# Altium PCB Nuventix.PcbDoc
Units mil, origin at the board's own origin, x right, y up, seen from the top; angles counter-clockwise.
Board outline 1849.93 x 1701.97 mil, 4 copper layers (Top Layer, MidLayer1, MidLayer2, Bottom Layer), stack 62 mil thick; 70 components, 33 nets, 174 pads, 56 vias.
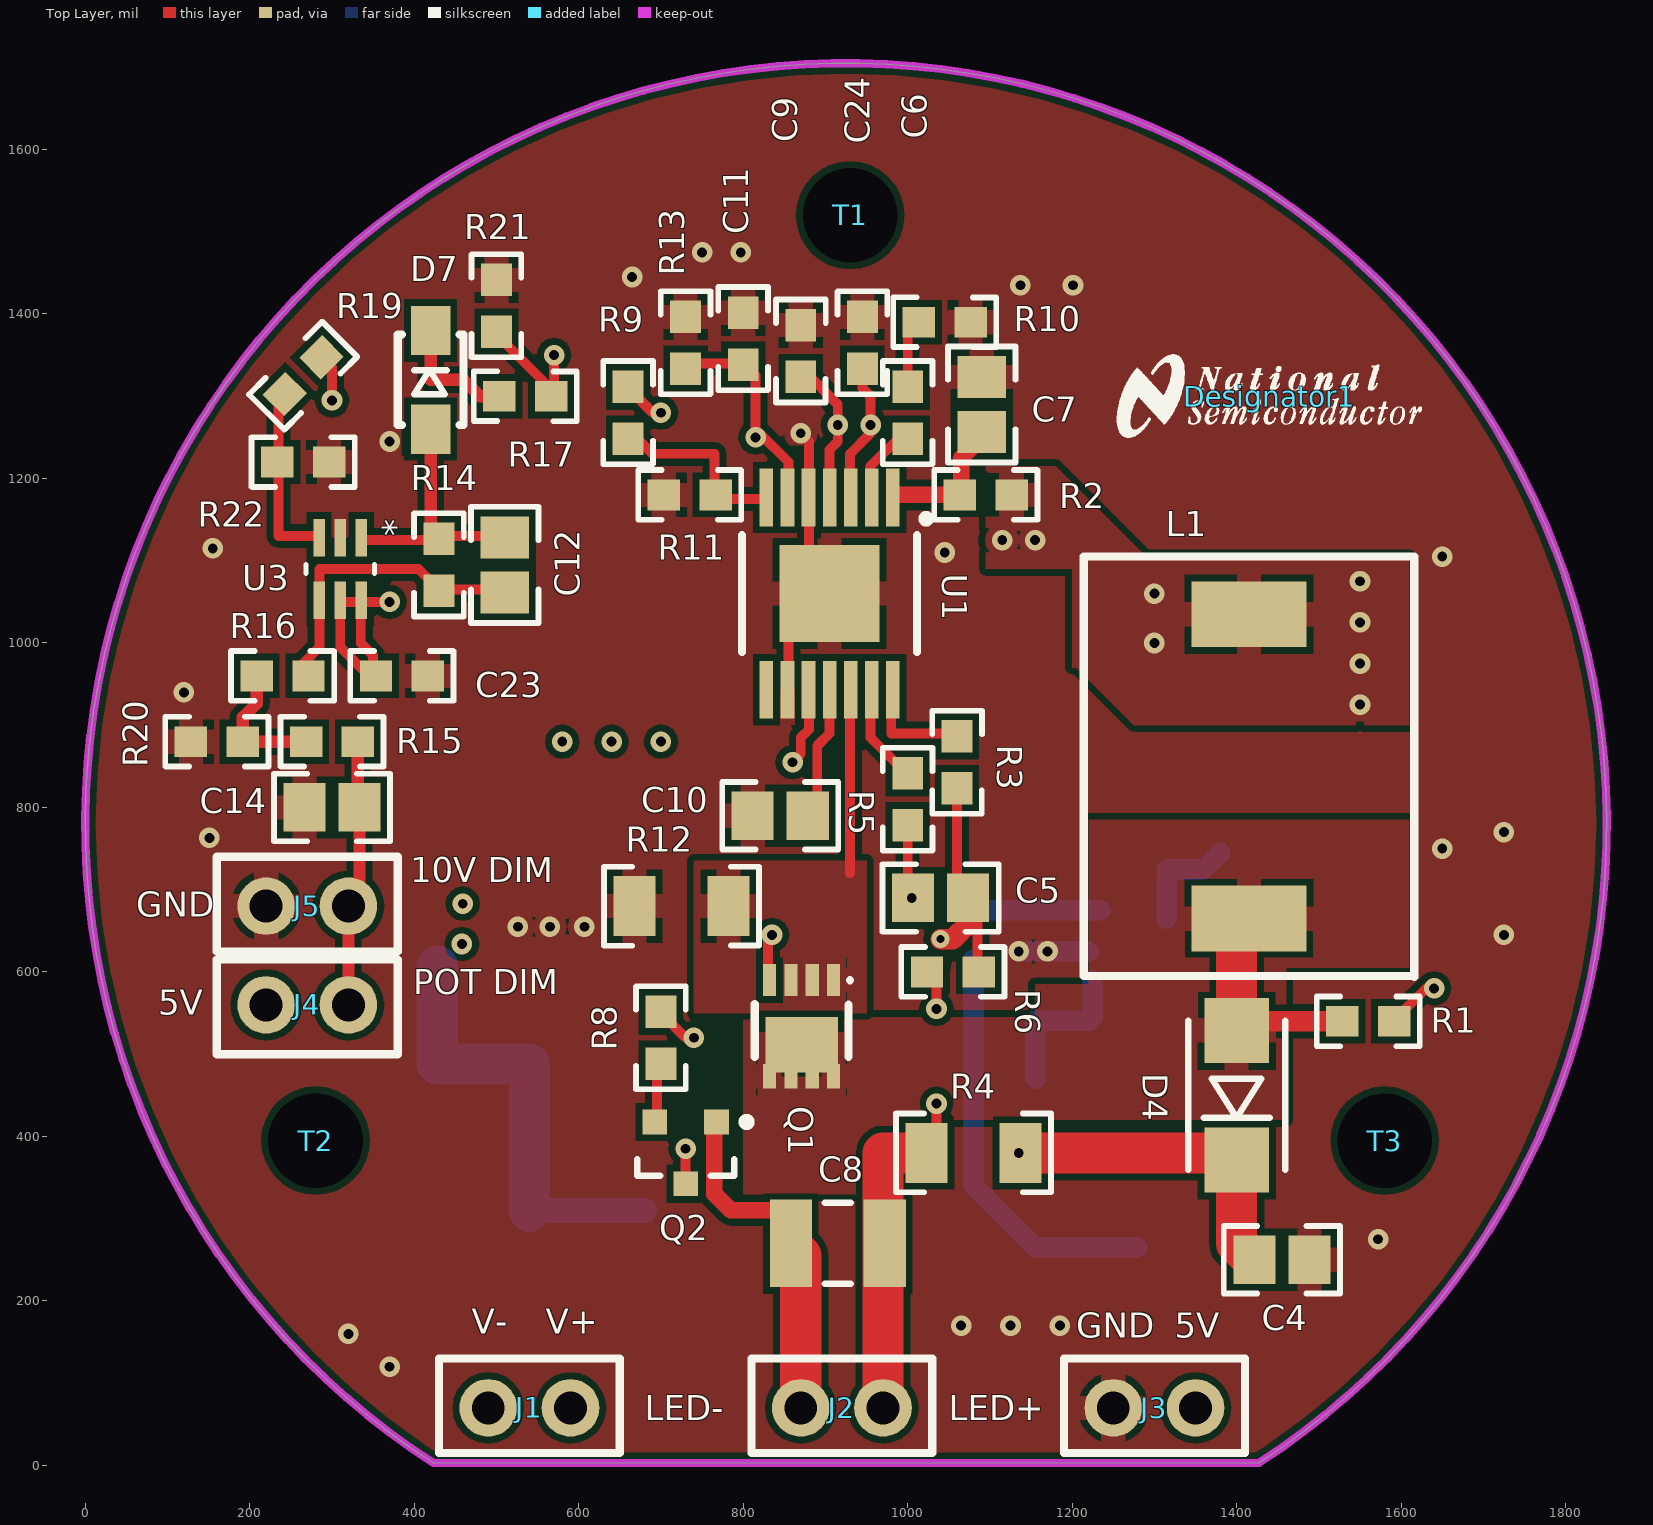
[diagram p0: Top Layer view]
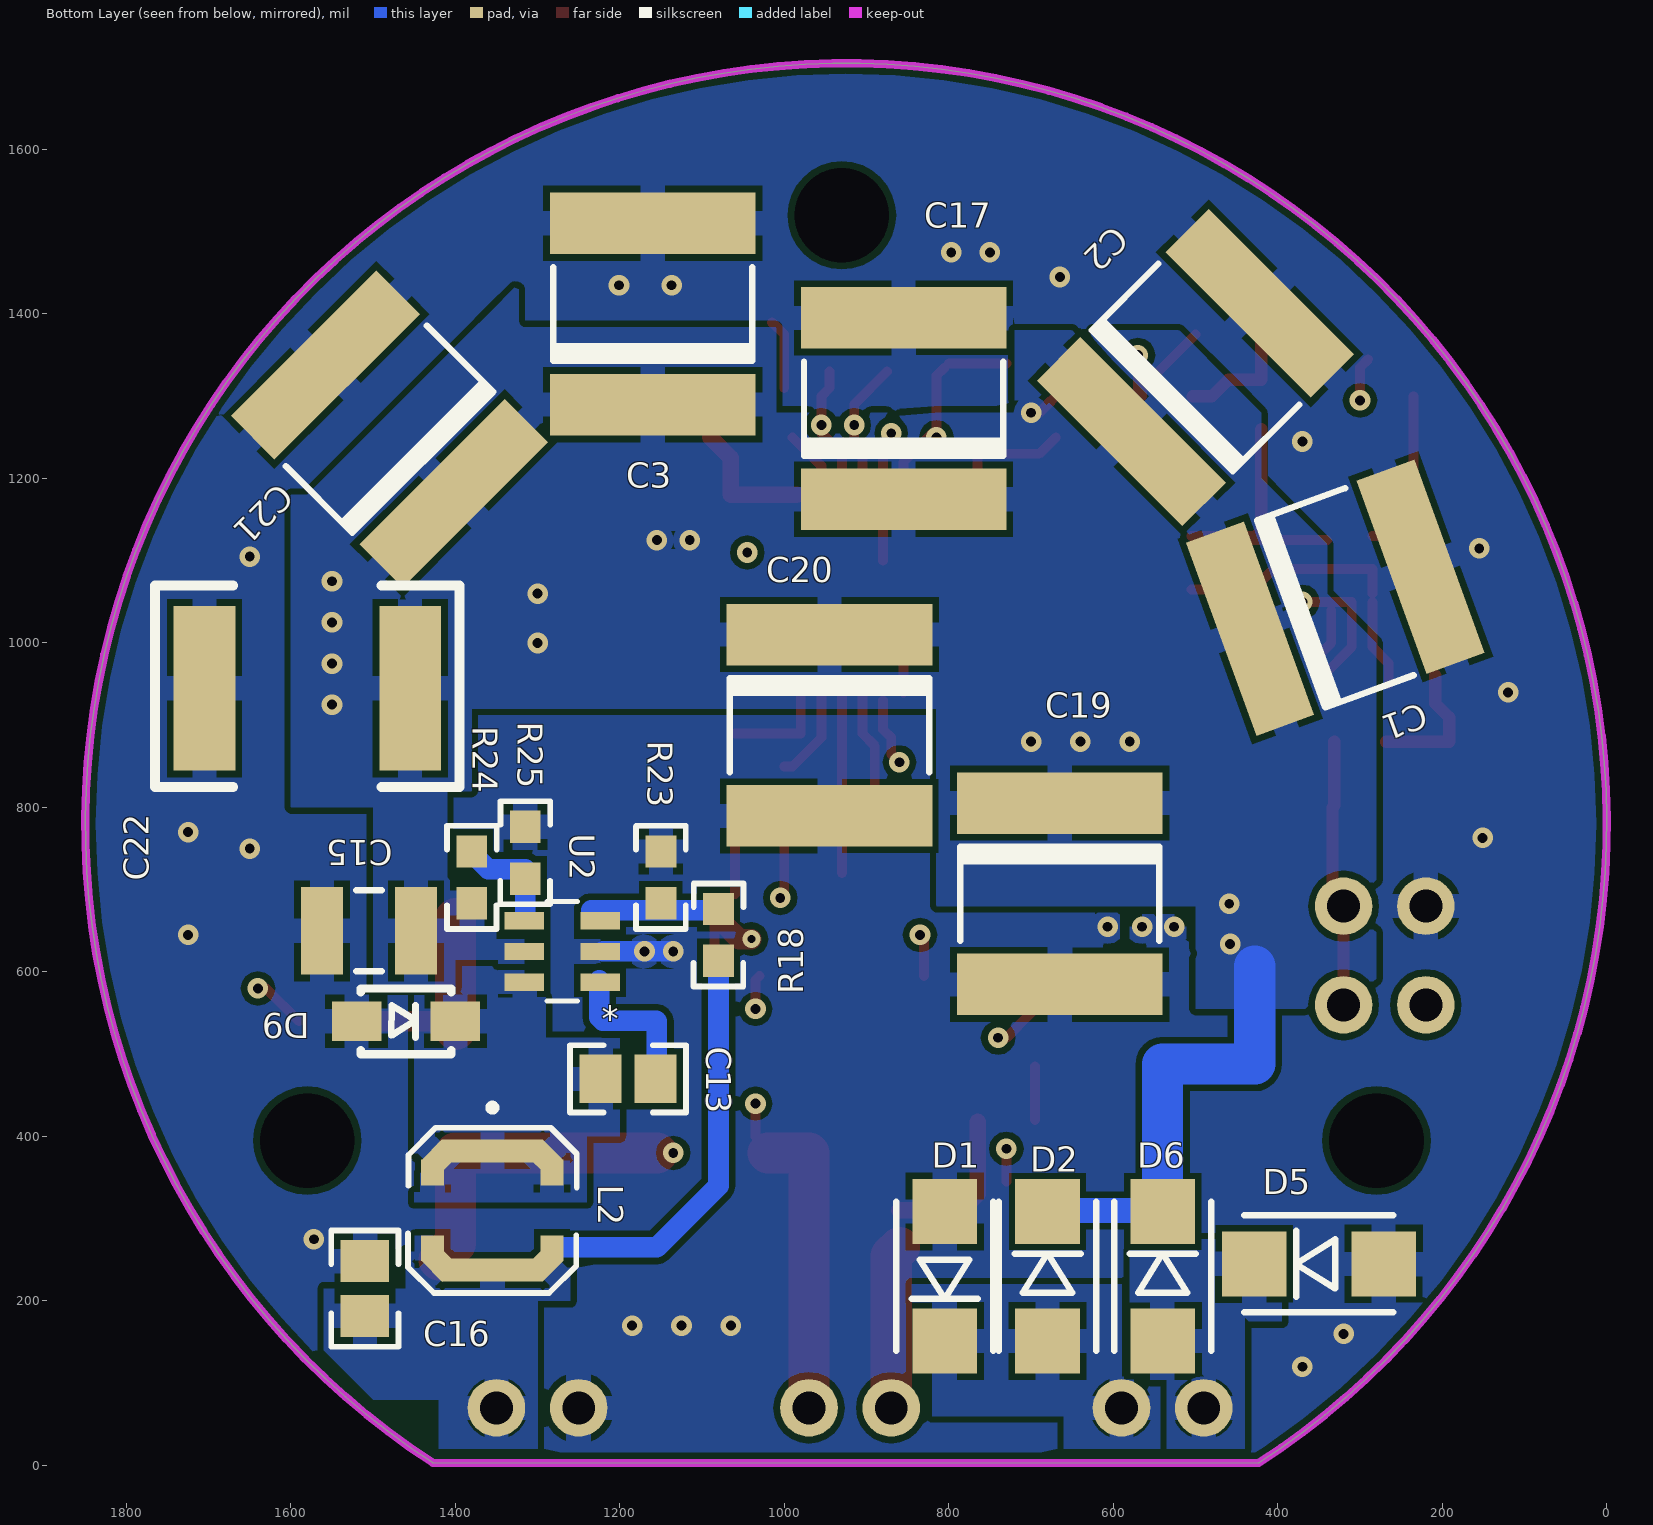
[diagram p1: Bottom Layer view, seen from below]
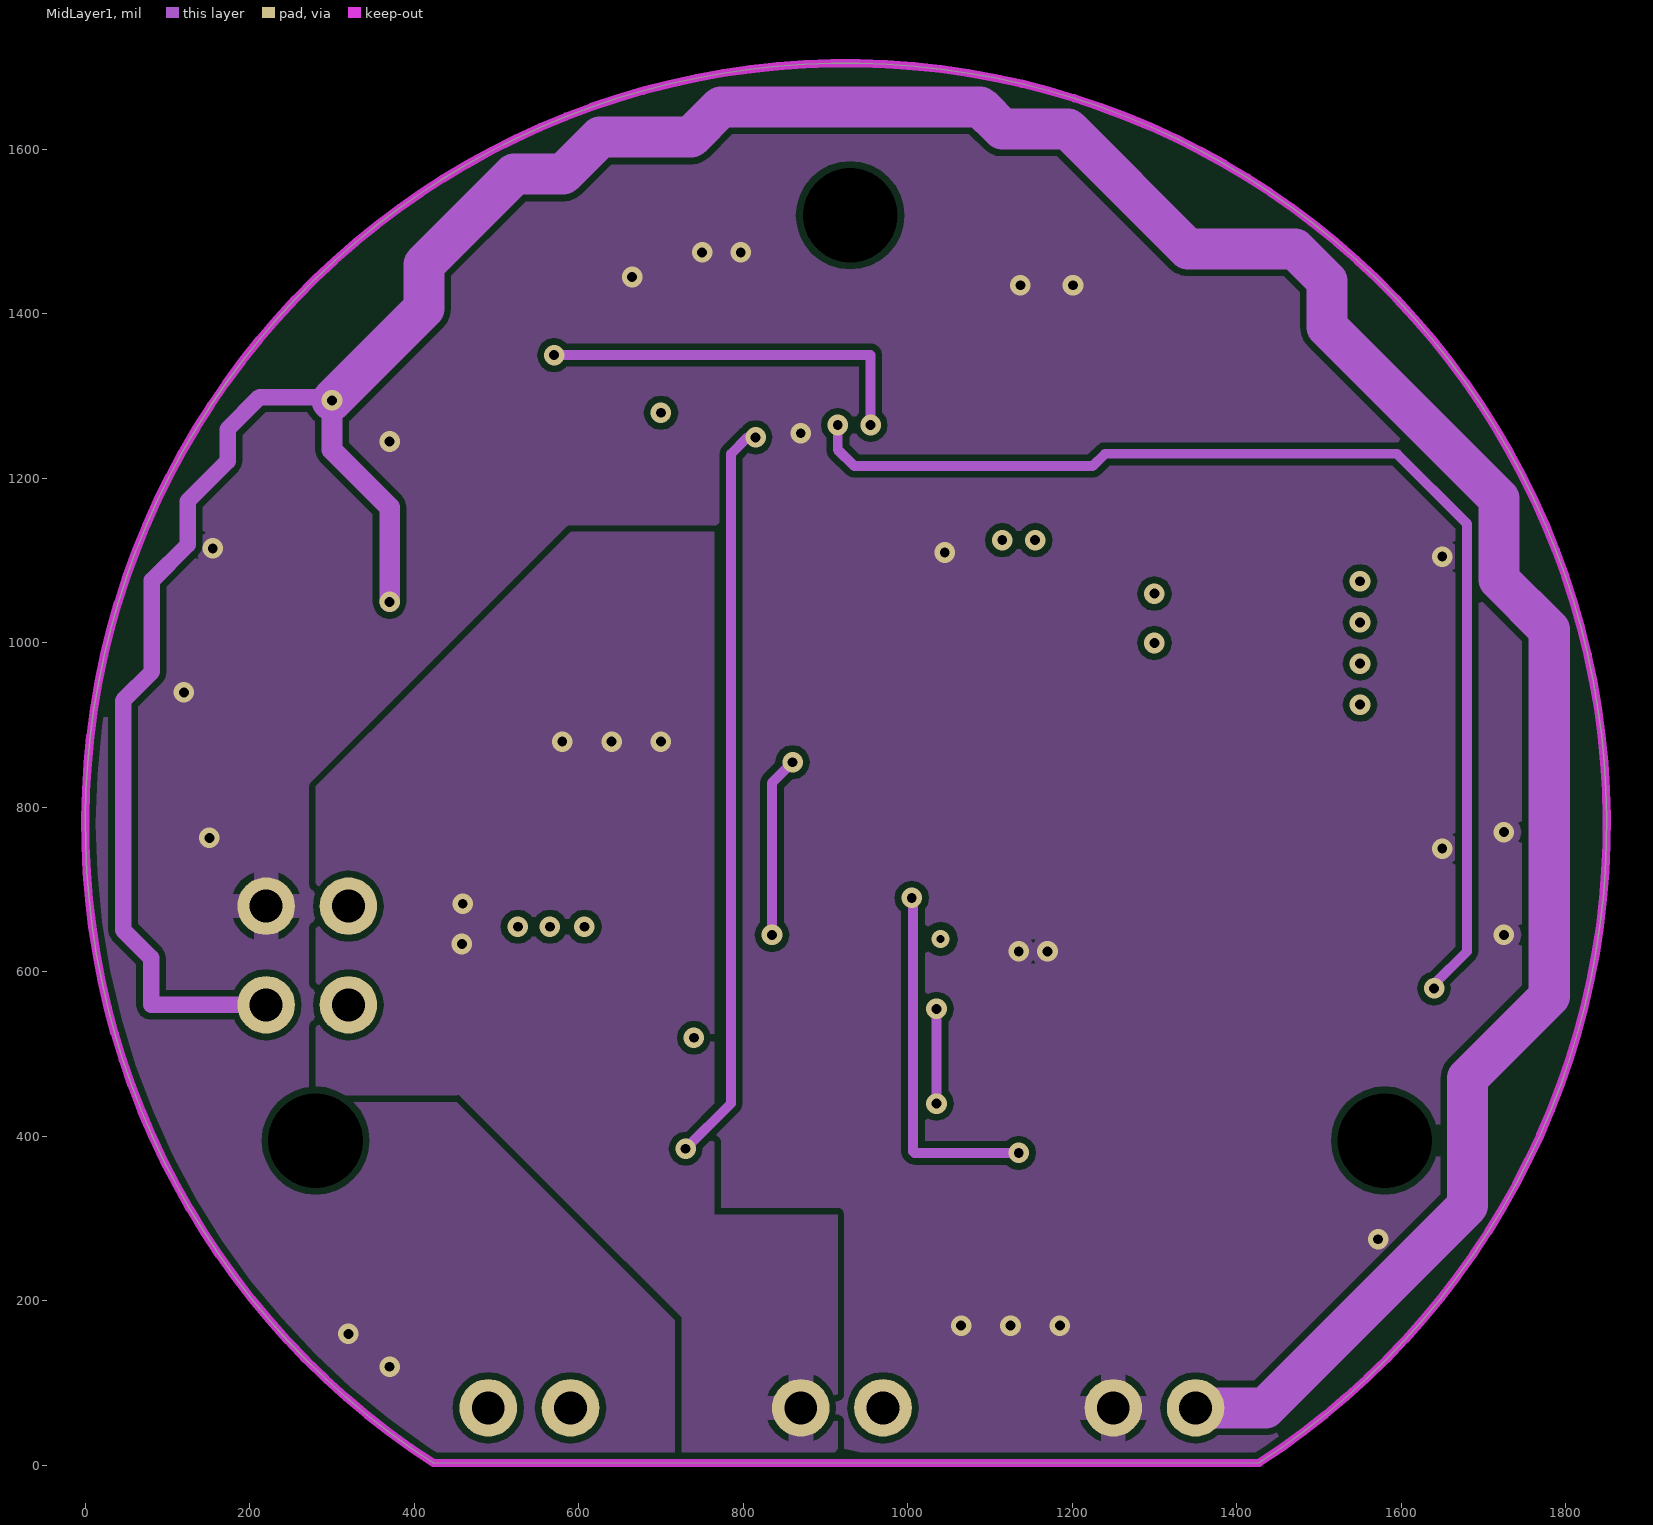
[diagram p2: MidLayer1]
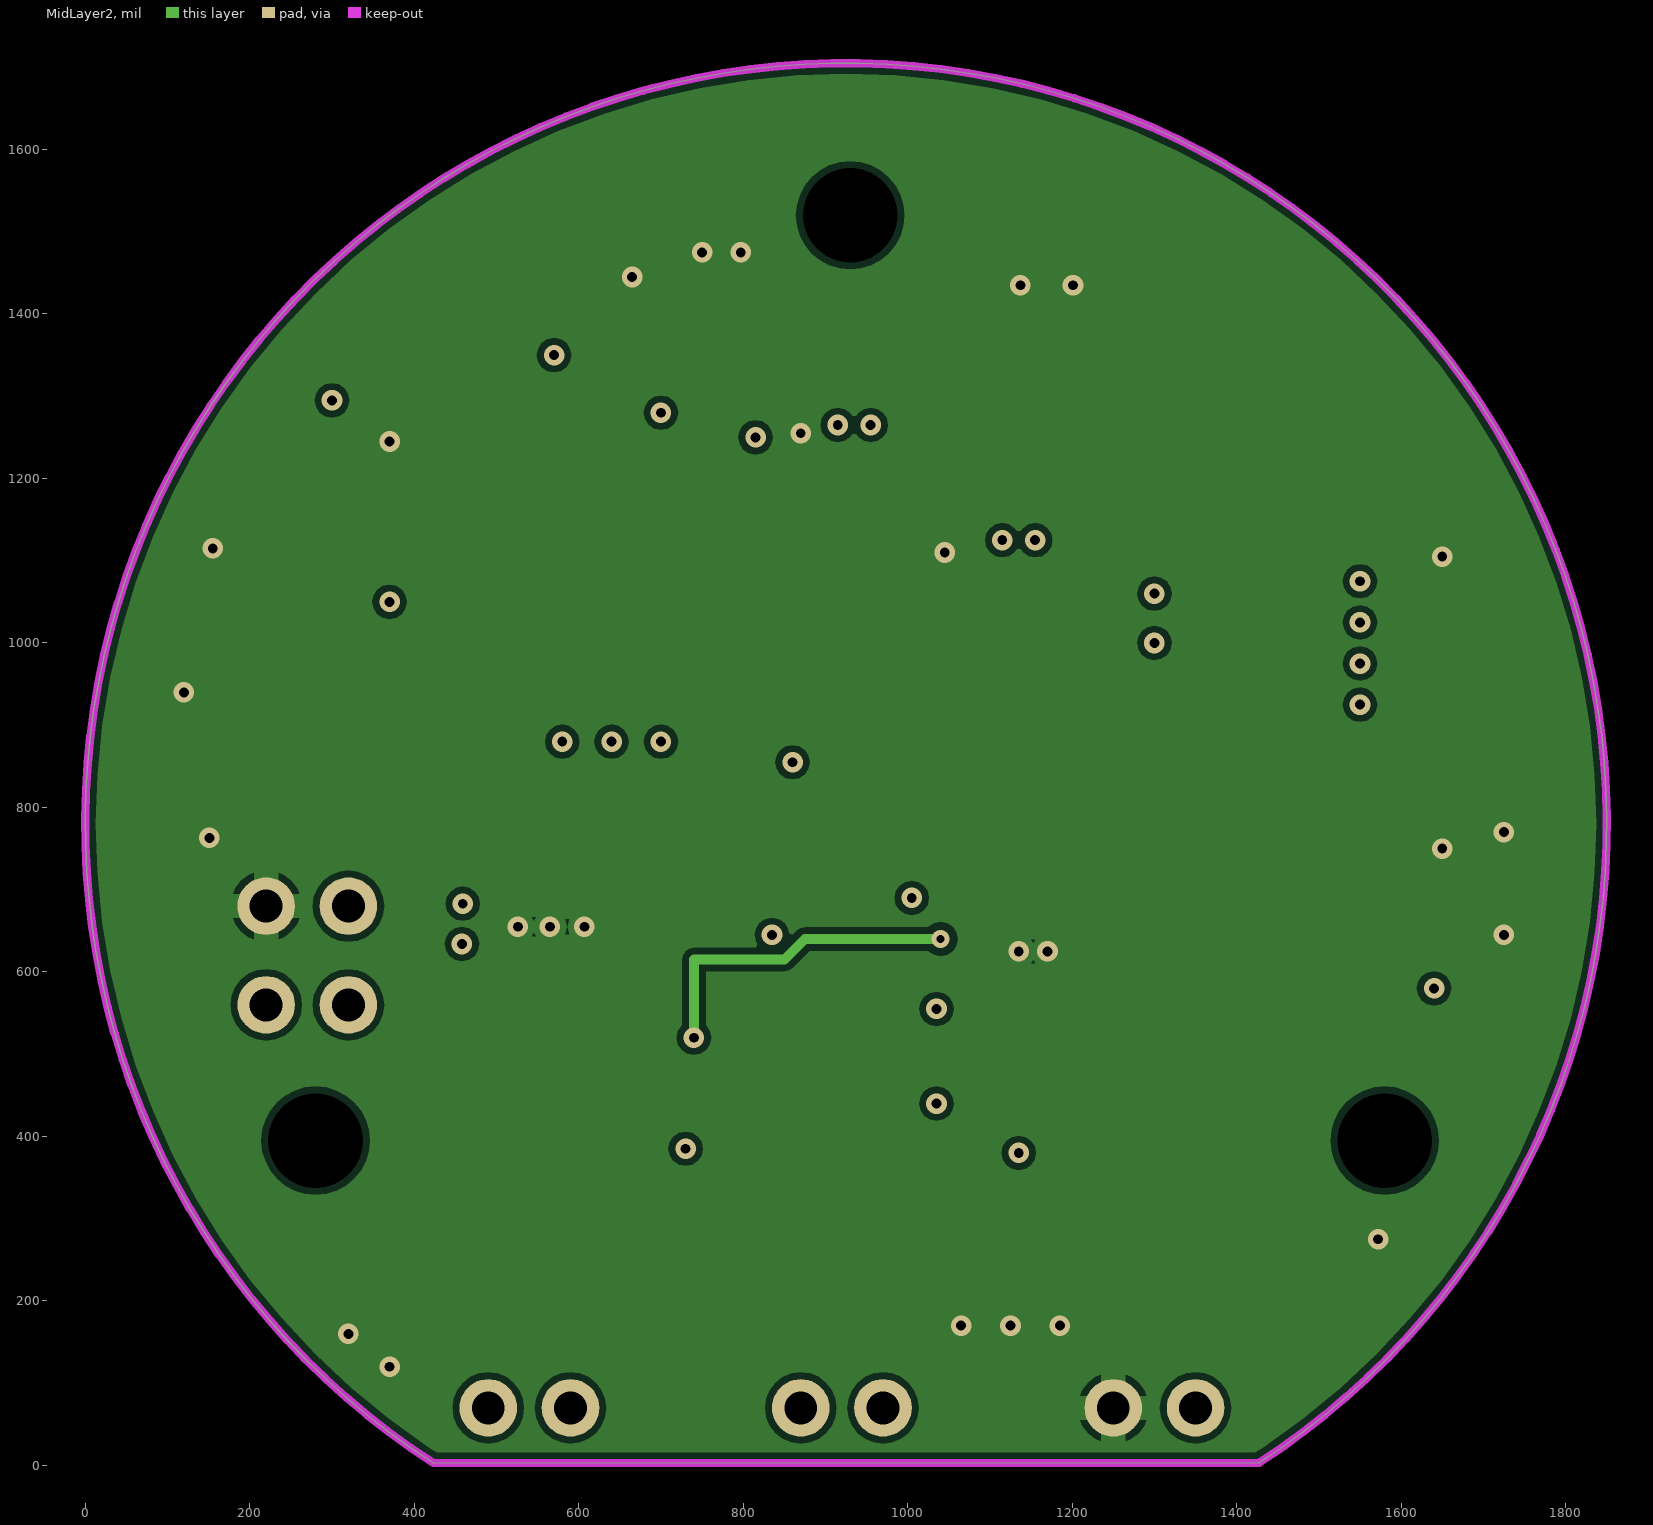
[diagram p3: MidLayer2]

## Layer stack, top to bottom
Top Layer: signal copper 1.4
Dielectric: core 12.6, FR-4, Dk 4.8
MidLayer1: signal copper 1.4
Dielectric: prepreg 31.2, FR-4, Dk 4.8
MidLayer2: signal copper 1.4
Dielectric: core 12.6, FR-4, Dk 4.8
Bottom Layer: signal copper 1.4

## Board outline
423.28,2.89 cw(c925,780) 1427.42,3.34 1427,3

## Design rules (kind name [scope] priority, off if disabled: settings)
Clearance [All] p1: gap=8
ComponentClearance [All] p1 off: gap=10 collisioncheckmode=3 verticalgap=10 showdistances=FALSE
ComponentClearance ComponentClearance_1 [All] p2 off: gap=10 collisioncheckmode=3 verticalgap=10 showdistances=FALSE
DiffPairsRouting DiffPairsRouting_1 [All] p2: maxlimit=10 minlimit=10 mostfreqgap=10 maxuncoupledlength=500
FanoutControl Fanout_LCC [IsLCC] p1: bgadir=Out bgaviamode=Centered fanoutstyle=Auto fanoutdirection=Alternating viagrid=1 // Fanout_LCC (Default Rule)
FanoutControl Fanout_BGA [IsBGA] p2: bgadir=Out bgaviamode=Centered fanoutstyle=Auto fanoutdirection=Alternating viagrid=1 // Fanout_BGA (Default Rule)
FanoutControl Fanout_Default [All] p4: bgadir=Out bgaviamode=Centered fanoutstyle=Auto fanoutdirection=Alternating viagrid=1 // Fanout_Default (Default Rule)
FanoutControl Fanout_Small [(CompPinCount < 5)] p5: bgadir=Out bgaviamode=Centered fanoutstyle=Auto fanoutdirection=OutThenIn viagrid=1 // Fanout_Small (Default Rule)
FanoutControl Fanout_BGA_1 [IsBGA] p6: bgadir=Out bgaviamode=Centered fanoutstyle=Auto fanoutdirection=Alternating viagrid=1 // Fanout_BGA (Default Rule)
FanoutControl Fanout_LCC_1 [IsLCC] p7: bgadir=Out bgaviamode=Centered fanoutstyle=Auto fanoutdirection=Alternating viagrid=1 // Fanout_LCC (Default Rule)
FanoutControl Fanout_SOIC_1 [IsSOIC] p8: bgadir=Out bgaviamode=Centered fanoutstyle=Auto fanoutdirection=Alternating viagrid=1 // Fanout_SOIC (Default Rule)
FanoutControl Fanout_Small_1 [(CompPinCount < 5)] p9: bgadir=Out bgaviamode=Centered fanoutstyle=Auto fanoutdirection=OutThenIn viagrid=1 // Fanout_Small (Default Rule)
FanoutControl Fanout_Default_1 [All] p10: bgadir=Out bgaviamode=Centered fanoutstyle=Auto fanoutdirection=Alternating viagrid=1 // Fanout_Default (Default Rule)
Height Height_1 [All] p2: minheight=0 maxheight=1000 prefheight=500
HoleSize [All] p1: absolutevalues=TRUE maxlimit=251 minlimit=8 maxpercent=80.000 minpercent=20.000
HoleSize HoleSize_1 [All] p2: absolutevalues=TRUE maxlimit=100 minlimit=1 maxpercent=80.000 minpercent=20.000
LayerPairs LayerPairs_1 [All] p2: enforce=TRUE
MinimumAnnularRing [All] p1: minimumring=6
MinimumSolderMaskSliver [All] p1 off: minsoldermaskwidth=10
PasteMaskExpansion PasteMaskExpansion_1 [All] p2: expansion=0
PlaneClearance PlaneClearance_1 [All] p2: clearance=20
PlaneConnect [All] p1: planeconnectstyle=Relief reliefexpansion=10 reliefentries=4 reliefconductorwidth=8 reliefairgap=10
PolygonConnect [All] p1: connectstyle=Relief reliefconductorwidth=30 reliefentries=4 polygonreliefangle="90 Angle"
PolygonConnect PolygonConnect_1 [All] p2: connectstyle=Relief reliefconductorwidth=10 reliefentries=4 polygonreliefangle="90 Angle"
RoutingPriority RoutingPriority_1 [All] p2: routingpriority=0
RoutingTopology RoutingTopology_1 [All] p2: topology=Shortest
RoutingVias [All] p1: holewidth=16 width=32 viastyle="Through Hole" minholewidth=10 minwidth=24 maxholewidth=20 maxwidth=40
ShortCircuit ShortCircuit_1 [All] p2: allowed=FALSE
SilkscreenOverComponentPads [All] p1 off: minsilkscreentomaskgap=10
SolderMaskExpansion [All] p1: expansion=4
SolderMaskExpansion SolderMaskExpansion_1 [All] p2: expansion=4
TestPointUsage [All] p1 off: valid=0 allowmultiple=FALSE
TestPointUsage TestPointUsage_1 [All] p2 off: valid=0 allowmultiple=FALSE
Testpoint [All] p1: side=15 testpointundercomponent=TRUE minsize=40 maxsize=100 preferedsize=60 minholesize=0 maxholesize=40 preferedholesize=32 testpointgrid=1 style=1023 order=0-112345678
Testpoint Testpoint_1 [All] p2: side=15 testpointundercomponent=TRUE minsize=40 maxsize=100 preferedsize=60 minholesize=0 maxholesize=40 preferedholesize=32 testpointgrid=1 style=1023 order=0-112345678
UnRoutedNet UnRoutedNet_1 [All] p2:
Width [All] p1: maxlimit=110 minlimit=6 preferedwidth=10 toplayer_prefwidth=15 bottomlayer_prefwidth=15 minimp=50.000000 maximp=50.000000 favimp=50.000000
15 further rules are at their usual default settings.

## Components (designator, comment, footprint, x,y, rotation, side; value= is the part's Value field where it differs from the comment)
C1 "TPSV686M025R0095" 7361-38 330,1055 r160 bottom
C2 "TPSV686M025R0095" 7361-38 500,1335 r135 bottom
C3 "TPSV686M025R0095" 7361-38 1160,1400 r90 bottom
C4 "08053C104KAT2A" 0805 1455,250 r0 top
C5 "08053C104KAT2A" 0805 1040,690 r0 top
C6 "06033D224KAT2A" 0603 1000,1280 r90 top
C7 "08053C104KAT2A" 0805 1090,1290 r90 top
C8 "GRM32ER61E226KE15L" 1210 915,270 r180 top
C9 "06031C102JAT2A" 0603 870,1355 r90 top
C10 "0805ZD225KAT2A" 0805 845,790 r180 top
C11 "06035A470JAT2A" 0603 800,1370 r90 top
C12 "0805ZD475KAT2A" 0805 510,1095 r270 top
C13 "08053C154KAT2A" 0805 1190,470 r180 bottom
C14 "0805ZD475KAT2A" 0805 300,800 r180 top
C15 "GRM32ER71H475KA88L" 1210 1505,650 r0 bottom
C16 "JMK212BJ476MG-T" 0805 1510,215 r90 bottom
C17 "TPSV686M025R0095" 7361-38 855,1285 r90 bottom
C19 "TPSV686M025R0095" 7361-38 665,695 r270 bottom
C20 "TPSV686M025R0095" 7361-38 945,900 r270 bottom
C21 "TPSV686M025R0095" 7361-38 1480,1260 r45 bottom
C22 "C5750X7R1H106M" 2220 1455,945 r0 bottom
C23 "0603YC104JAT2A" 0603 385,960 r0 top
C24 "0603YC104JAT2A" 0603 945,1365 r270 top
D1 "MBRA160T3G" SMA 805,230 r270 bottom
D2 "MBRA160T3G" SMA 680,230 r90 bottom
D4 "MBRA160T3G" SMA 1400,450 r270 top
D5 "MBRA160T3G" SMA 350,245 r0 bottom
D6 "MBRA160T3G" SMA 540,230 r90 bottom
D7 "1N5819HW-7-F" SOD-123 420,1320 r90 top
D9 "MBR130T1G" SOD-123 1460,540 r180 bottom
Designator1 "Comment" Logo_Overlay_Small 1440,1300 r0 top
J1 "VAC" "0.1\" header 2-pos" 490,70 r180 top
J2 "LED" "0.1\" header 2-pos" 870,70 r180 top
J3 "5V" "0.1\" header 2-pos" 1250,70 r180 top
J4 "POT DIM" "0.1\" header 2-pos" 320,560 r0 top (schematic designator J1)
J5 "10V DIM" "0.1\" header 2-pos" 220,680 r180 top (schematic designator J1)
L1 "MSS1038-473MLB" MSS1038 1415,850 r270 top
L2 "LPS4018-153MLB" LPS4018 1355,310 r270 bottom
Q1 "SI7414DN" "1212-8 Powerpack_smask" 910,590 r270 top
Q2 "CMPT3906" SOT-23 730,380 r270 top
R1 "CRCW060341k2FKEA" 0603 1560,540 r180 top
R2 "CRCW060310R0FKEA" 0603 1095,1180 r0 top
R3 "CRCW06031k00JNEA" 0603 1060,855 r90 top
R4 "ERJ-8RSJR15V" 1206 1080,380 r180 top
R5 "CRCW06031k00JNEA" 0603 1000,810 r90 top
R6 "CRCW060310R0FKEA" 0603 1055,600 r180 top
R8 "RT0603BRD07174KL" 0603 700,520 r270 top
R9 "CRCW060390k9FKEA" 0603 660,1280 r270 top
R10 "CRCW060310R0FKEA" 0603 1045,1390 r0 top
R11 "CRCW060320k0JNEA" 0603 735,1180 r180 top
R12 "LVK12R050FER" 1206 725,680 r180 top
R13 "CRCW06038k66FKEA" 0603 730,1365 r90 top
R14 "CRCW060310k0JNEA" 0603 430,1095 r270 top
R15 "CRCW06034k99FKEA" 0603 300,880 r180 top
R16 "CRCW060310k0JNEA" 0603 240,960 r180 top
R17 "CRCW0603100kFKEA" 0603 535,1300 r180 top
R18 "CRCW06035k62FKEA" 0603 1080,645 r90 bottom
R19 "CRCW060310k0JNEA" 0603 265,1325 r45 top
R20 "CRCW06034k99FKEA" 0603 160,880 r180 top
R21 "CRCW060311k8FKEA" 0603 500,1410 r90 top
R22 "CRCW060310k0JNEA" 0603 265,1220 r0 top
R23 "CRCW06031k02FKEA" 0603 1150,715 r270 bottom
R24 "CRCW060369k8FKEA" 0603 1380,715 r270 bottom
R25 "CRCW060310k0JNEA" 0603 1315,745 r90 bottom
T1 "TOOLING HOLE" "4-40 Mounting Hole"#1 935,1515 r0 top
T2 "TOOLING HOLE" "4-40 Mounting Hole"#2 280,415 r0 top
T3 "TOOLING HOLE" "4-40 Mounting Hole"#3 1405,395 r0 top
U1 "LM3429" TSSOP-14_EP 905,1060 r180 top
U2 "LM2842" MK06A 1270,625 r0 bottom
U3 "LMH6601MG" MAA06A 310,1090 r270 top

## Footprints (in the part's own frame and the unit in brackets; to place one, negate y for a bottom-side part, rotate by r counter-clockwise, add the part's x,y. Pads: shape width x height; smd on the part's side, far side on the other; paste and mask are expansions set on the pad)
"0.1\" header 2-pos" [mil] "standard 0.1\" headerstrip, two position"
  round 70 hole 40: 1(-100,0) 2(0,0)
  silkscreen extent -160,-60 60,55
"4-40 Mounting Hole"#1 [mil] "Tooling Hole"
  round 0 hole 115 unplated: 0(-5,5)
"4-40 Mounting Hole"#2 [mil] "Tooling Hole"
  round 0 hole 115 unplated: 0(0,-20)
"4-40 Mounting Hole"#3 [mil] "Tooling Hole"
  round 0 hole 115 unplated: 0(175,0)
0603 [mm] "0603 from SM-752 data"
  rect 1x0.95 smd: 1(-0.8,0) 2(0.8,0)
  silkscreen extent -1.59,-0.77 1.59,0.77, body extent -0.88,-0.48 0.87,0.48, height 0.85
0805 [mm] "0805 from SM-752 data"
  rect 1.3x1.5 smd: 1(-0.85,0) 2(0.85,0)
  silkscreen extent -1.79,-1.04 1.79,1.04, body extent -1.1,-0.72 1.1,0.72, height 1.1
1206 [mm] "1206 from SM-752 data"
  rect 1.3x1.85 smd: 1(-1.45,0) 2(1.45,0)
  silkscreen extent -2.39,-1.22 2.39,1.22, body extent -1.7,-0.9 1.7,0.9, height 1.35
1210 [mm] "1210 from SM-752 data"
  rect 1.3x2.7 smd: 1(-1.45,0) 2(1.45,0)
  silkscreen extent -0.4,-1.25 0.4,1.25, body extent -1.7,-1.35 1.7,1.35, height 1.35
"1212-8 Powerpack_smask" [mil]
  rect 39x16 smd mask+2: 1(0,0) 1(0,-26) 1(0,-52) 2(0,-78)
  rect 68x88 smd: 3(78.5,-39)
  rect 30x16 smd mask+2: 3(117,-26) 3(117,0) 3(117,-78) 3(117,-52)
  silkscreen extent 0,-96 93,20
2220 [mil]
  rect 75x200 smd: 1(0,0) 2(250,0)
  silkscreen extent -60,-125 310,120
7361-38 [mm] "Medium density IPC based on AVX dimensions for TPS series"
  rect 1.9x6.35 smd: 1(-2.8,0) 2(2.8,0)
  silkscreen extent -1.45,-3.08 1.45,3.07, body extent -3.75,-3.15 3.75,3.15, height 3.8
Logo_Overlay_Small [mil]
  silkscreen extent -186,-50 185,51
LPS4018 [mil]
  rect 28x123 smd: 1(-72.5,0) 2(72.5,0)
  rect 35.5x28 smd rot 135: 1(-64,-64) 2(64,64)
  rect 35.5x28 smd rot 45: 1(-64,64) 2(64.5,-63.5)
  rect 31.5x28 smd: 1(-46,-72.5) 1(-46,72.5) 2(46,-72.5) 2(46,72.5)
  silkscreen extent -129,-103 101,103
MAA06A [mil]
  rect 46x14 smd: 1(-38,25.59) 2(-38,0) 3(-38,-25.59) 4(38,-25.59) 5(38,0) 6(38,25.59)
  silkscreen extent -5,-42 5,42
MK06A [mil]
  rect 48x21 smd: 1(-46,37.4) 2(-46,0) 3(-46,-37.4) 4(46,-37.4) 5(46,0) 6(46,37.4)
  silkscreen extent -18,-60 18,60
MSS1038 [mil]
  rect 80x140 smd: 1(-185,0) 2(185,0)
  silkscreen extent -255,-201 256,201
SMA [mm] "Molded Diode, 2-Leads, Body 4.3x2.6mm, IPC Medium Density, based on OnSemi component dimensions and land pattern"
  rect 2x2 smd: 1(-2,0) 2(2,0)
  silkscreen extent -2.3,-1.5 2.3,1.5, body extent -2.29,-1.46 2.28,1.46, height 2.27
SOD-123 [mil]
  rect 60x48 smd: 1(-60,0) 2(60,0)
  silkscreen extent -55,-40 55,40
SOT-23 [mm] "SOT23, 3-Leads, Body 3.0x2.6mm (max), Pitch 0.95mm, IPC Medium Density, from National MF03A"
  rect 0.76x0.76 smd: 1(-0.955,0.953) 2(-0.955,-0.953) 3(0.955,0)
  silkscreen extent -1.08,-1.5 0.7,2.01, body extent -0.7,-1.52 0.7,1.52, height 1.12
TSSOP-14_EP [mm]
  rect 0.42x1.78 smd mask+0.051: 1(-1.95,-2.97) 2(-1.3,-2.97) 3(-0.65,-2.97) 4(0,-2.97) 5(0.65,-2.97) 6(1.3,-2.97) 7(1.95,-2.97) 8(1.95,2.97) 9(1.3,2.97) 10(0.65,2.97) 11(0,2.97) 12(-0.65,2.97) 13(-1.3,2.97) 14(-1.95,2.97)
  rect 3.1x3 smd: 15(0,0)
  silkscreen extent -3.1,-2.42 2.7,1.8

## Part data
C1 C2 C3 C17 C19 C20 C21: "Polarized Capacitor"
C4 C5 C6 C7 C8 C9 C10 C11 C12 C13 C14 C15 C16 C22 C23 C24: "Capacitor"
D1 D2 D4 D5 D6 D9: "Schottky Diode"
D7: "Vr = 40V, Io = 1A, Vf = 0.45V"
J1 J2 J3 J4 J5: library part "CONN 1X2"
L1 L2: "Magnetic-Core Inductor"
Q1: library part SI7478DP
Q2: "PNP Bipolar Transistor"
R1 R2 R3 R4 R5 R6 R8 R9 R10 R11 R12 R13 R14 R15 R16 R17 R18 R19 R20 R21 R22 R23 R24 R25: "Resistor"
U2: library part LM284X_0
U3: "2.4V R-R Out CMOS Video OpAmp with Shutdown"

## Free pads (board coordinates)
  rect 400x150 on Top Solder: 0(1415,1025) 1(1415,675)

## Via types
v1: diameter 25, hole 12, Top Layer to Bottom Layer, 55 vias
v2: diameter 22, hole 10, Top Layer to Bottom Layer, 1 vias

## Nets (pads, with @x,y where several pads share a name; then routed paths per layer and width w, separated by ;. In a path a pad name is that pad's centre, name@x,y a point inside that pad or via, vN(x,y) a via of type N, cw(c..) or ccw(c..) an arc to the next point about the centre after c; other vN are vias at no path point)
5V: C16.1 C23.1 J3.1 J4.1 L2.2 R18.1 R19.2 U3.5 U3.6 | length 5327.9
  Top Layer w12: R19.2@290,1345 300,1335 v1(300,1295) ; U3.6@335,1040 335,1000 350,985 350,960 345,960 310,995 310,1050 v1(370,1050)
  MidLayer1 w20: J4.1 80,560 80,617 46,651 46,930 81,965 81,1076 124.5,1119.5 124.5,1172.5 173,1221 173,1259.96 212.04,1299 296,1299 v1(300,1295)
  MidLayer1 w25: v1(300,1295) 300,1235 370,1165 v1(370,1050)
  MidLayer1 w50: v1(300,1295) 411.68,1406.68 411.68,1460 521.68,1570 580.76,1570 625.76,1615 736.26,1615 773.13,1651.87 1088.13,1651.87 1115.14,1624.86 1195.14,1624.86 1340.83,1479.17 1470.83,1479.17 1510,1440 1510,1384.39 1719,1175.39 1719,1077.1 1780,1016.1 1780,570 1680.89,470.89 1680.89,315.89 1435,70 J3.1
  Bottom Layer w25: R18.1@1080,615 1080,340 1155,265 L2.2@1280,265
GND: C1.2 C2.2 C3.2 C4.2 C7.2 C9.2 C10.2 C11.2 C14.2 C15.2 C16.2 C17.2 C19.2 C20.2 C21.2 C22.2 C23.2 C24.1 D1.1 D5.1 D9.1 J3.2 J5.2 R10.2 R11.2 R12.2 R13.2 R20.2 R21.2 R22.2 R23.1 R25.2 U1.5 U1.9 U1.15 U2.2 U3.2 | length 314.1
  Top Layer w12: U1.9@855,940 U1.15@855,1035 ; v1(870,1255) 880,1245 U1.5@880,1200 ; U1.15@880,1100 U1.5@880,1175
  Bottom Layer w25: v1(1135,625) U2.2@1220,625
  other v1: 370,120 320,160 1065,170 1125,170 1185,170 1572,275 1170,625 1725,645 526,655 565,655 607,655 1650,750 151,763 1725,770 120,940 1650,1105 1045,1110 155,1115 370,1245 1137,1435 1201,1435 665,1445 750,1475 797,1475
NetC4_1: C4.1 C5.1 D4.2 R4.1 R5.1 | length 895.8
  Top Layer w12: C5.1@1000,695 R5.1@1000,780
  Top Layer w50: R4.1@1155,380 D4.2@1400,380 ; D4.2@1400,370 1400,270 C4.1@1420,250
  MidLayer1 w12: v1@1006.54,690 1006.54,381.54 1008.07,380 v1(1135,380)
  other v1: 1005,690
NetC5_2: C5.2 R3.1 R6.1 R8.1 | length 716.1
  Top Layer w12: R8.1@700,550 730,520 v1(740,520) ; C5.2@1060,695 R3.1@1060,820 ; R6.1@1085,600 C5.2@1085,685
  Top Layer w25: v2(1040,640) 1055,640 1075,660 C5.2@1075,665
  MidLayer2 w12: v1(740,520) 740,615 850,615 875,640 v2(1040,640)
NetC6_1: C6.1 U1.2 | length 74.5
  Top Layer w12: U1.2@955,1190 955,1215 C6.1@990,1250
NetC6_2: C6.2 R10.1 | length 86.2
  Top Layer w12: C6.2@1000,1310 1000,1375 R10.1@1015,1390
NetC7_1: C7.1 R2.1 U1.1 | length 160.4
  Top Layer w20: U1.1@985,1180 1065,1180 1065,1225 C7.1@1090,1250
NetC8_1: C8.1 J2.1 R4.2 R6.2 | length 566.2
  Top Layer w12: R4.2@1025,390 1035,400 v1(1035,440) ; R6.2@1030,595 1035,590 v1(1035,555)
  Top Layer w50: J2.1 C8.1@970,270 ; C8.1@970,275 970,380 R4.2@1020,380
  MidLayer1 w12: v1(1035,440) v1(1035,555)
NetC9_1: C9.1 R1.1 U1.4 | length 1658.6
  Top Layer w12: C9.1@875,1330 915,1290 915,1245 905,1235 U1.4@905,1185 ; R1.1@1590,540 1630,580 v1(1640,580)
  MidLayer1 w12: v1(915,1265) 915,1235 935,1215 1225,1215 1240,1230 1595,1230 1680,1145 1680,625 1640,585 v1(1640,580)
NetC10_1: C10.1 U1.11 | length 141.2
  Top Layer w12: C10.1@890,805 890,875 905,890 U1.11@905,940
NetC12_1: C12.1 D7.1 R14.1 U3.1 | length 302.6
  Top Layer w12: U3.1@340,1125 R14.1@430,1125 ; R14.1@430,1130 C12.1@505,1130
  Top Layer w15: D7.1 420,1136.5 R14.1
NetC12_2: C12.2 R14.2 R16.1 U3.4 | length 368.6
  Top Layer w12: R16.1@265,950 265,975 285,995 U3.4@285,1050 ; U3.4@285,1060 285,1090 405,1090 430,1065 C12.2@505,1065
NetC13_1: C13.1 D9.2 L2.1 U2.6
NetC13_2: C13.2 U2.1 | length 187.1
  Bottom Layer w25: C13.2@1155,470 1155,540 1155.5,540.5 1220.5,540.5 1225,545 U2.1@1225,590
NetC14_1: C14.1 J4.2 J5.1 R15.1 | length 326.4
  Top Layer w15: J4.2 J5.1 333.46,693.46 C14.1 331.5,801.97 R15.1
NetC24_2: C24.2 R17.1 R21.1 U1.3 | length 771.4
  Top Layer w12: R21.1@500,1375 565,1310 R17.1@565,1300 ; R17.1@570,1300 v1(570,1350) ; U1.3@930,1195 930,1230 955,1255 955,1300 945,1310 C24.2@945,1330
  MidLayer1 w12: v1(570,1350) 955,1350 v1(955,1265)
NetD2_2: 
NetD4_1: D4.1 L1.2 Q1.3 R1.2 | length 245
  Top Layer w25: D4.1@1415,540 R1.2@1525,540
  Top Layer w50: D4.1@1400,530 L1.2@1400,665
NetD7_2: D7.2 R17.2 | length 151.8
  Top Layer w15: D7.2 420,1320 460,1320 480,1300 R17.2
NetQ1_1: Q1.1 R12.1 U1.12 | length 220
  Top Layer w12: 930,720 U1.12@930,940
NetQ1_4: Q1.2 U1.10 | length 355.7
  Top Layer w12: Q1.2@830,595 830,640 v1(835,645) ; v1(860,855) 870,865 870,885 880,895 U1.10@880,930
  MidLayer1 w12: v1(835,645) 835,830 v1(860,855)
NetQ2_2: Q2.2 R8.2 | length 65
  Top Layer w12: Q2.2@695,420 R8.2@695,485
NetR3_2: R3.2 U1.14 | length 130
  Top Layer w12: U1.14@980,940 980,890 R3.2@1060,890
NetR5_2: R5.2 U1.13 | length 109.5
  Top Layer w12: U1.13@955,935 955,885 990,850 R5.2@1000,850
NetR9_2: R9.2 R11.1 U1.7 | length 213.3
  Top Layer w12: R9.2@670,1250 690,1230 765,1230 R11.1@765,1185 ; R11.1@765,1175 U1.7@830,1175
NetR15_2: R15.2 R16.2 R20.1 | length 164.1
  Top Layer w15: R16.2 208.5,926.5 191.5,909.5 R20.1 R15.2
NetR18_2: R18.2 R23.2 U2.3 | length 155
  Bottom Layer w25: R18.2@1080,675 1235,675
NetR19_1: R19.1 R22.1 U3.3 | length 220
  Top Layer w12: R19.1@235,1300 235,1130 U3.3@285,1130
NetR24_1: R24.1 R25.1 U2.4 | length 123.3
  Bottom Layer w25: U2.4@1315,665 R25.1@1315,715 ; R25.1@1315,725 1360,725 R24.1@1380,745
OVP: C11.1 Q2.3 R13.1 U1.6 | length 1191.8
  Top Layer w12: Q2.3@730,345 v1(730,385) ; R13.1@730,1340 C11.1@800,1340 ; C11.1@805,1335 815,1325 v1(815,1250) 820,1255 855,1220 U1.6@855,1190
  MidLayer1 w12: v1(730,385) 785,440 785,1230 805,1250 v1(815,1250)
V+: C1.1 C2.1 C3.1 C8.2 C15.1 C17.1 C19.1 C20.1 C21.1 C22.1 D2.2 D6.2 J2.2 L1.1 Q2.1 R2.2 R9.1 R24.2 U2.5 | length 992.7
  Top Layer w12: R9.1@660,1310 690,1280 v1(700,1280)
  Top Layer w20: Q2.1@765,417.6 765,330 785,310 C8.2@860,310
  Top Layer w50: C8.2@860,265 870,255 J2.2
  Bottom Layer w30: D6.2@540,310 D2.2@680,310
  Bottom Layer w50: 428,607 428,488 540,488 540,310 D6.2
  other v1: 458,634 459,683 580,880 640,880 700,880 1550,925 1550,975 1300,1000 1550,1025 1300,1060 1550,1075 1115,1125 1155,1125
VAC+: D1.2 D2.1 J1.1
VAC-: D5.2 D6.1 J1.2
pads on no net: T1.0 T2.0 T3.0 U1.8

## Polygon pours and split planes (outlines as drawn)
NetQ1_1 on Top Layer "Top Layer-No Net" (solid, pour order 1000): 740,735 950,735 950,550 740,550 740,735
NetD4_1 on Top Layer "Top Layer-No Net" (solid, pour order 1001): 800,545 1155,545 1155,585 1220,585 1220,785 1610,785 1610,605 1460,605 1460,420 985,420 985,330 800,330 800,545
V+ on Top Layer "Top Layer-No Net" (solid, pour order 1002): 1095,1215 1180,1215 1290,1105 1610,1105 1610,900 1275,900 1205,970 1200,970 1200,1090 1095,1090 1095,1215
GND on Top Layer "Top Layer-No Net" (solid, remove dead copper, pour order 1003): -5,1725 1855,1725 1855,-5 -5,-5 -5,1725
V+ on MidLayer1 "Top Layer-No Net" (solid, pour order 1004): 915,20 910,15 725,15 725,180 455,450 355,450 280,450 280,760 280,825 590,1135 765,1135 765,305 915,305 915,15
GND on MidLayer1 "Top Layer-No Net" (solid, remove dead copper, pour order 1005): -5,1725 1865,1725 1865,5 1860,0 -5,0 -5,1725
GND on MidLayer2 "Top Layer-No Net" (solid, remove dead copper, pour order 1006): -15,1725 1875,1725 1875,-20 -15,-20 -15,1725
VAC- on Bottom Layer "Top Layer-No Net" (solid, pour order 1000): 395,275 580,275 580,110 535,110 535,20 440,20 440,180 435,175 395,175 395,275
VAC+ on Bottom Layer "Top Layer-No Net" (solid, pour order 1001): 590,220 845,220 845,110 820,110 820,60 660,60 660,20 540,20 540,100 590,100 590,220
NetC13_1 on Bottom Layer "Top Layer-No Net" (solid, pour order 1003): 1290,610 1450,610 1450,320 1240,320 1240,400 1200,400 1200,520 1290,520 1290,610
5V on Bottom Layer "Top Layer-No Net" (solid, pour order 1004): 1260,260 1460,260 1460,215 1560,215 1560,140 1500,80 1420,80 1420,20 1300,20 1300,200 1260,200 1260,260
V+ on Bottom Layer "Top Layer-No Net" (solid, pour order 1002): 346,535 ccw(c355,535) 361.36,528.64 367.73,535 500,535 500,460 280,460 280,1000 340,1060 340,1120 420,1200 420,1280 520,1380 720,1380 720,1280 1010,1280 1010,1440 1320,1440 1580,1180 1600,1180 1600,800 1500,800 1500,580 1400,580 1400,615 1290,615 1290,640 1350,640 1350,715 1410,715 1410,820 1380,820 1380,920 815,920 815,680 500,680 500,555 359,555 352.16,551.84 351.64,551.36 348.64,548.36 346,542
GND on Bottom Layer "Top Layer-No Net" (solid, remove dead copper, pour order 1005): 0,1720 1850,1720 1850,-5 0,-5 0,1720

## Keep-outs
Keep-Out Layer:
  lines w10: 423.28,2.89 cw(c925,780) 1427.42,3.34 ; 424,3 1427,3

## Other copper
Top Layer:
  text "880" at 2610,-2220 h80
  text ".Layer_Name" at 2620,-2440 h80
Bottom Layer:
  text "880" at 2610,-2220 h80
  text ".Layer_Name" at 2620,-2440 h80

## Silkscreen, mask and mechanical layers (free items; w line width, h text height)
Top Overlay:
  text "GND" at 62,667 h30
  text "5V" at 89,548 h30
  text "V-" at 470,160 h30
  text "V+" at 560,160 h30
  text "GND" at 1205,155 h30
  text "5V" at 1325,155 h30
  text "LED-" at 680,55 h30
  text "LED+" at 1050,55 h30
  text "880" at 2610,-2220 h30
  text ".Layer_Name" at 2620,-2440 h30
Bottom Overlay:
  text "880" at 2610,-2220 h30
  text ".Layer_Name" at 2620,-2440 h30
Top Paste:
  text "881" at 2610,-2220 h80
  text ".Layer_Name" at 2620,-2440 h80
Bottom Paste:
  text "881" at 2610,-2220 h80
  text ".Layer_Name" at 2620,-2440 h80
Top Solder:
  text "880" at 2610,-2220 h80
  text ".Layer_Name" at 2620,-2440 h80
Bottom Solder:
  text "880" at 2610,-2220 h80
  text ".Layer_Name" at 2620,-2440 h80
M1 Board Outline:
  lines w10: 423.28,2.89 cw(c925,780) 1427.42,3.34 ; 424,3 1427,3
M2 Board Dimensions:
  rectangle: -450,-1335 -75,-1210
  rectangle: -575,-1210 -450,-1085
  lines w7: -575,-1210 425,-1210 ; -450,-1335 -450,-1085 ; -325,-1335 -325,-1085 ; -75,-1335 -75,-1085 ; 175,-1335 175,-1085 ; -575,-1335 -575,-1085 425,-1085 425,-1335 -575,-1335
  lines w10: -575,-1400 -575,-1380 ; -515,-1410 -575,-1390 ; -515,-1370 -575,-1390 ; -350.92,-1390 -575,-1390 ; 200.92,-1390 425,-1390 ; 365,-1410 425,-1390 ; 365,-1370 425,-1390 ; 425,-1400 425,-1380
  text "1000 (mil)" at -340.92,-1425.99 h60
M4 Gerber Information:
  drawing of 34 lines, arcs and shapes, not listed
  text "ALL ARTWORK VIEWED FROM TOP SIDE" at 2225,-1772.82 h80
  text "BOARD NAME" at 1478.5,-1996.67 h80
  text ".PRJ_Title" at 2605,-1996.67 h80
  text "ARTWORK #" at 1483.5,-2220 h80
  text ".prj_BasePN" at 2855,-2220 h80
  text ".pcb_minorRev" at 3410,-2220 h80
  text "LAYER NAME" at 1493.5,-2440 h80
  text "PRINT DATE" at 1483.5,-2659.5 h80
  text ".Print_Date" at 2610,-2659.5 h80
M12 Stackup:
  lines w17: -140,4695.17 5020,4695.17 ; -140,5007.37 5020,5007.37 ; 5076,3423 5076,5241 ; 5080,3441 cw(c4979,3441) 4979,3340 -99,3340 cw(c-99,3441) -200,3441 -200,5259 cw(c-99,5259) -99,5360 4979,5360 cw(c4979,5259) 5080,5259
  text "Layer Stack Up Detail for: Ref_Design.PcbDoc" at -140,5100.18 h115
  text "Layer" at -140,4890.87 h72
  text "Name" at -140,4746.87 h72
  text "Top Layer" at -140,4471.67 h101
  text "MidLayer1" at -140,4185 h101
  text "MidLayer2" at -140,3898.33 h101
  text "Bottom Layer" at -140,3611.67 h101
M14 Fab Notes:
  text "Fabrication Layer and Board Outline" at 6075,4130 h200
  text "MTL: FR4" at 6080,3835 h200
  text "Layers: 4" at 6065,3525 h200
  text "Thickness: .063 +/- 10%" at 6035,3215 h200
  text "Copper 1 oZ both sides, 1 oZ thru Vias" at 6065,2900 h200
  text "Finish: Gold" at 6080,2545 h200
  text "Solder Mask: Green both sides" at 6070,2225 h200
  text "Silkscreen: White both sides" at 6070,1915 h200
  text "Route to Board Outine (Keep Out Layer)" at 6070,1595 h200
  text "Hole Size: +/- .002" at 6060,1255 h200
  text "Min Trace width: .006" at 6060,925 h200
  text "Min Spacing: .008" at 6050,595 h200
M16 Title Block:
  drawing of 59 lines, arcs and shapes, not listed
  text "1" at 91.34,5765 h70
  text "2" at 2587,5765 h70
  text "3" at 5526.34,5545 h70
  text "4" at 8033.01,5545 h70
  text "5" at 10532,5545 h70
  text "6" at 13037,5545 h70
  text "A" at -1065,4622 h70
  text "B" at -1065,2242 h70
  text "C" at -1065,-133 h70
  text "PROJECT TITLE:" at 10695,-2295 h45
  text "Nuventix Board" at 10745,-2415 h70
  text "D" at -1065,-2503 h70
  text "REV:" at 9205,-2585 h45
  text "SCALE:" at 9880,-2585 h45
  text "DESIGNED FOR:" at 10695,-2585 h45
  text ".PCB_MinorRev" at 9230,-2740 h70
  text "NTS" at 10165,-2740 h70
  text ".PRJ_Customer" at 10745,-2740 h70
  text "PRINT DATE:" at 9205,-2895 h45
  text "PADC NUMBER:" at 10695,-2895 h45
  text "FAB DRAWING NUMBER:" at 12240,-2895 h45
  text "National Semiconductor and/or its licensors do not warrant the accuracy or completeness of this" at 4465,-2897 h45
  text "specification or any information contained therein. National and/or its licensors do not warrant that" at 4465,-2989.6 h45
  text ".PRINT_DATE" at 9230,-3035 h70
  text ".PRJ_PADC" at 10745,-3034.99 h70
  text "551" at 12290,-3034.99 h70
  text ".PRJ_BasePN" at 12485,-3034.99 h70
  text "this design will meet the specifications, will be suitable for your application or fit for any particular" at 4465,-3082.2 h45
  text "purpose, or will operate in an implementation. National and/or its licensors do not warrant that the" at 4465,-3174.8 h45
  text "FILE NAME:" at 9205,-3195 h45
  text "design is production worthy. You should completely validate and test your design implementation" at 4465,-3267.4 h45
  text ".Pcb_File_Name_No_Path" at 9230,-3328.33 h70
  text "to confirm the system functionality for your application." at 4465,-3360 h45
  text "1" at 91.34,-3535 h70
  text "2" at 2587,-3535 h70
  text "3" at 5076.34,-3535 h70
  text "4" at 7583.01,-3535 h70
  text "5" at 10082,-3535 h70
  text "6" at 12587,-3535 h70
Drill Drawing:
  text ".legend" at 5635,-810 h60
  text "Drill Table" at 5660,-995 h60

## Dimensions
423.28,2.89 to 1427.42,3.34 on M2 Board Dimensions
423.28,2.89 to 423.28,2.89 on M2 Board Dimensions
